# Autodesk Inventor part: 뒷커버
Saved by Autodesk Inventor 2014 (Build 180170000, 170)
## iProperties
Created: 2026-07
Part Number: 뒷커버
Material: 알루미늄 6061
Document SubType Name: Modeling
Designer: dg
Density: 2.71 g/cm^3
Appearance: 알루미늄 - 평지
Mass: 95.5479 g
Surface Area: 99.2053 cm^2
Volume: 35.2575 cm^3
Author: jhkim
Creation Date: 2026-07-02
Sending System: Autodesk Inventor 2027
Preprocessor: ST-DEVELOPER v20.1
Author: dg
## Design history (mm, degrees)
node "뒷커버1"
node "솔리드1"
node "기준1"
